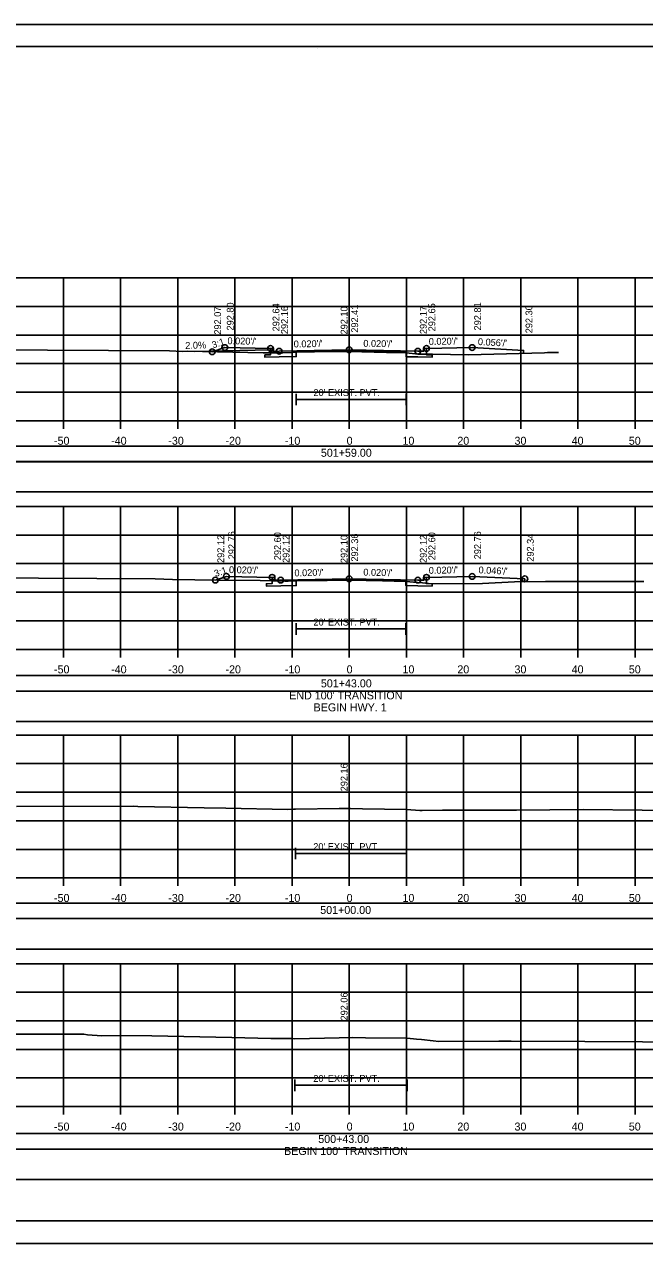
# Model space of a CAD drawing. Extents: x 1370538 to 1372872, y 376220 to 381127.
# Drawn here: x 1372651.8 to 1372760.3, y 376433.8 to 376647.1 of the extents above; entities that cross this region are included whole.
import ezdxf

# ---------------------------------------------------------------- set-up
doc = ezdxf.new("R2010")
doc.units = 0
for name, color, linetype in [('R_Border', 7, 'Continuous'), ('R_Border Notes', 7, 'Continuous'), ('R_Border PE', 7, 'Continuous'), ('R_Border Prem', 7, 'Continuous'), ('R_Dimension', 7, 'Continuous'), ('R_Fin Surface', 7, 'Continuous'), ('R_Grid', 7, 'Continuous'), ('R_No Plot', 7, 'Continuous'), ('R_Water', 7, 'Continuous'), ('R_Xsect Elev', 7, 'Continuous'), ('R_Xsect Slope', 7, 'Continuous'), ('T_Detection Zones', 7, 'Continuous')]:
    doc.layers.add(name, color=color, linetype=linetype)

msp = doc.modelspace()

# ---------------------------------------------------------------- linework, layer by layer
at = {"layer": 'R_Border'}
for p, q in [((1372699.38, 376582.48), (1372699.38, 376580.48)), ((1372699.38, 376581.48), (1372718.58, 376581.48)), ((1372718.58, 376582.48), (1372718.58, 376580.48)), ((1372699.38, 376542.32), (1372699.38, 376540.32)), ((1372699.38, 376541.32), (1372718.57, 376541.32)), ((1372718.57, 376542.32), (1372718.57, 376540.32)), ((1372699.23, 376503.04), (1372699.23, 376501.04)), ((1372718.67, 376503.04), (1372718.67, 376501.04)), ((1372699.23, 376502.04), (1372718.67, 376502.04)), ((1372699.13, 376462.47), (1372699.13, 376460.47)), ((1372718.78, 376462.47), (1372718.78, 376460.47)), ((1372699.13, 376461.47), (1372718.78, 376461.47))]:
    msp.add_line(p, q, dxfattribs=at)
for points in [[(1372722.15, 376590.4), (1372722.15, 376589.31), (1372723.15, 376589.29), (1372723.15, 376588.87), (1372720.65, 376588.92), (1372718.58, 376588.96), (1372718.58, 376589.79), (1372708.65, 376589.99), (1372699.38, 376589.8), (1372699.38, 376588.97), (1372696.38, 376588.91), (1372693.88, 376588.86), (1372693.88, 376589.28), (1372694.88, 376589.3), (1372694.88, 376590.39)], [(1372722.15, 376550.35), (1372722.15, 376549.26), (1372723.15, 376549.24), (1372723.15, 376548.82), (1372720.65, 376548.87), (1372718.57, 376548.91), (1372718.57, 376549.74), (1372708.65, 376549.94), (1372699.38, 376549.76), (1372699.38, 376548.92), (1372696.65, 376548.87), (1372694.15, 376548.82), (1372694.15, 376549.24), (1372695.15, 376549.26), (1372695.15, 376550.35)]]:
    msp.add_lwpolyline(points, dxfattribs=at)
at = {"layer": 'R_Border Notes'}
for p, q in [((1372550.65, 376643.21), (1372866.83, 376643.21)), ((1372703.17, 376642.95), (1372703.17, 376642.95)), ((1372703.17, 376642.95), (1372703.17, 376642.95)), ((1372866.83, 376437.75), (1372550.65, 376437.75))]:
    msp.add_line(p, q, dxfattribs=at)
at = {"layer": 'R_Border Prem'}
for p, q in [((1372558.65, 376577.75), (1372858.65, 376577.75)), ((1372658.65, 376576.35), (1372658.65, 376577.75)), ((1372668.65, 376576.35), (1372668.65, 376577.75)), ((1372678.65, 376576.35), (1372678.65, 376577.75)), ((1372688.65, 376576.35), (1372688.65, 376577.75)), ((1372698.65, 376576.35), (1372698.65, 376577.75)), ((1372708.65, 376576.35), (1372708.65, 376577.75)), ((1372718.65, 376576.35), (1372718.65, 376577.75)), ((1372728.65, 376576.35), (1372728.65, 376577.75)), ((1372738.65, 376576.35), (1372738.65, 376577.75)), ((1372748.65, 376576.35), (1372748.65, 376577.75)), ((1372758.65, 376576.35), (1372758.65, 376577.75)), ((1372558.65, 376537.75), (1372858.65, 376537.75)), ((1372658.65, 376536.35), (1372658.65, 376537.75)), ((1372668.65, 376536.35), (1372668.65, 376537.75)), ((1372678.65, 376536.35), (1372678.65, 376537.75)), ((1372688.65, 376536.35), (1372688.65, 376537.75)), ((1372698.65, 376536.35), (1372698.65, 376537.75)), ((1372708.65, 376536.35), (1372708.65, 376537.75)), ((1372718.65, 376536.35), (1372718.65, 376537.75)), ((1372728.65, 376536.35), (1372728.65, 376537.75)), ((1372738.65, 376536.35), (1372738.65, 376537.75)), ((1372748.65, 376536.35), (1372748.65, 376537.75)), ((1372758.65, 376536.35), (1372758.65, 376537.75)), ((1372558.65, 376497.75), (1372858.65, 376497.75)), ((1372658.65, 376496.35), (1372658.65, 376497.75)), ((1372668.65, 376496.35), (1372668.65, 376497.75)), ((1372678.65, 376496.35), (1372678.65, 376497.75)), ((1372688.65, 376496.35), (1372688.65, 376497.75)), ((1372698.65, 376496.35), (1372698.65, 376497.75)), ((1372708.65, 376496.35), (1372708.65, 376497.75)), ((1372718.65, 376496.35), (1372718.65, 376497.75)), ((1372728.65, 376496.35), (1372728.65, 376497.75)), ((1372738.65, 376496.35), (1372738.65, 376497.75)), ((1372748.65, 376496.35), (1372748.65, 376497.75)), ((1372758.65, 376496.35), (1372758.65, 376497.75)), ((1372558.65, 376457.75), (1372858.65, 376457.75)), ((1372658.65, 376456.35), (1372658.65, 376457.75)), ((1372668.65, 376456.35), (1372668.65, 376457.75)), ((1372678.65, 376456.35), (1372678.65, 376457.75)), ((1372688.65, 376456.35), (1372688.65, 376457.75)), ((1372698.65, 376456.35), (1372698.65, 376457.75)), ((1372708.65, 376456.35), (1372708.65, 376457.75)), ((1372718.65, 376456.35), (1372718.65, 376457.75)), ((1372728.65, 376456.35), (1372728.65, 376457.75)), ((1372738.65, 376456.35), (1372738.65, 376457.75)), ((1372748.65, 376456.35), (1372748.65, 376457.75)), ((1372758.65, 376456.35), (1372758.65, 376457.75))]:
    msp.add_line(p, q, dxfattribs=at)
at = {"layer": 'R_Dimension'}
for points in [[(1372602.41, 376590.38), (1372677.18, 376589.99), (1372679.5, 376589.89), (1372680.3, 376589.9), (1372693.58, 376589.65), (1372697.01, 376589.66), (1372698.59, 376589.71), (1372699.38, 376589.74), (1372702.58, 376589.79), (1372708.67, 376589.85), (1372715.18, 376589.69), (1372718.58, 376589.61), (1372720.75, 376589.43), (1372721.29, 376589.38), (1372723.23, 376589.38), (1372729.52, 376589.3), (1372742.79, 376589.65), (1372743.35, 376589.68), (1372743.98, 376589.69), (1372744.51, 376589.69), (1372745.24, 376589.69)], [(1372623.62, 376550.37), (1372674.71, 376550.11), (1372677.73, 376549.99), (1372685.54, 376549.87), (1372693.08, 376549.78), (1372697.37, 376549.71), (1372697.98, 376549.71), (1372699.38, 376549.75), (1372704.81, 376549.81), (1372708.7, 376549.85), (1372714.44, 376549.72), (1372718.57, 376549.63), (1372720.59, 376549.44), (1372721.49, 376549.38), (1372722.52, 376549.3), (1372723.29, 376549.2), (1372731.94, 376549.3), (1372737.55, 376549.57), (1372743.01, 376549.63), (1372744.67, 376549.64), (1372747.12, 376549.64), (1372747.84, 376549.64), (1372760.19, 376549.62)], [(1372650.44, 376510.24), (1372670.9, 376510.3), (1372671.63, 376510.26), (1372683.29, 376510.01), (1372687.07, 376509.96), (1372697.82, 376509.74), (1372698.88, 376509.76), (1372699.23, 376509.76), (1372706.86, 376509.88), (1372708.85, 376509.91), (1372710.97, 376509.87), (1372718.67, 376509.74), (1372720.97, 376509.58), (1372721.43, 376509.55), (1372724.97, 376509.59), (1372737.91, 376509.62), (1372749.59, 376509.71), (1372759.89, 376509.64), (1372770.62, 376509.57)], [(1372645.59, 376470.4), (1372662.23, 376470.4), (1372662.85, 376470.33), (1372665.35, 376470.13), (1372668.65, 376470.2), (1372674.1, 376470.13), (1372688.11, 376469.81), (1372694.94, 376469.67), (1372697.44, 376469.64), (1372698.7, 376469.64), (1372699.13, 376469.63), (1372706.87, 376469.78), (1372709.23, 376469.82), (1372711.52, 376469.79), (1372718.78, 376469.7), (1372720.41, 376469.55), (1372721.3, 376469.46), (1372723.31, 376469.24), (1372724.32, 376469.11), (1372734.8, 376469.19), (1372735.84, 376469.19), (1372736.07, 376469.19), (1372736.24, 376469.19), (1372736.98, 376469.19), (1372749.87, 376469.15), (1372759.96, 376469.09), (1372804.27, 376468.71)]]:
    msp.add_lwpolyline(points, dxfattribs=at)
at = {"layer": 'R_Fin Surface'}
msp.add_line((1372739.38, 376550.09), (1372739.38, 376549.59), dxfattribs=at)
for points in [[(1372684.67, 376589.82), (1372686.88, 376590.55), (1372694.88, 376590.39), (1372695.38, 376590.39), (1372695.38, 376589.89), (1372696.38, 376589.91), (1372708.65, 376590.16), (1372720.65, 376589.92), (1372721.65, 376589.9), (1372721.65, 376590.4), (1372722.15, 376590.4), (1372730.15, 376590.56)], [(1372739.14, 376589.56), (1372739.14, 376590.06), (1372730.15, 376590.56)], [(1372685.22, 376549.87), (1372687.15, 376550.51), (1372695.15, 376550.35), (1372695.65, 376550.35), (1372695.65, 376549.85), (1372696.65, 376549.87), (1372708.65, 376550.11), (1372720.65, 376549.87), (1372721.65, 376549.85), (1372721.65, 376550.35), (1372722.15, 376550.35), (1372730.15, 376550.51), (1372739.38, 376550.09)]]:
    msp.add_lwpolyline(points, dxfattribs=at)
at = {"layer": 'R_Grid'}
for p, q in [((1372558.65, 376602.75), (1372858.65, 376602.75)), ((1372658.65, 376577.75), (1372658.65, 376602.75)), ((1372668.65, 376577.75), (1372668.65, 376602.75)), ((1372678.65, 376577.75), (1372678.65, 376602.75)), ((1372688.65, 376577.75), (1372688.65, 376602.75)), ((1372698.65, 376577.75), (1372698.65, 376602.75)), ((1372708.65, 376577.75), (1372708.65, 376602.75)), ((1372718.65, 376577.75), (1372718.65, 376602.75)), ((1372728.65, 376577.75), (1372728.65, 376602.75)), ((1372738.65, 376577.75), (1372738.65, 376602.75)), ((1372748.65, 376577.75), (1372748.65, 376602.75)), ((1372758.65, 376577.75), (1372758.65, 376602.75)), ((1372558.65, 376597.75), (1372858.65, 376597.75)), ((1372558.65, 376592.75), (1372858.65, 376592.75)), ((1372558.65, 376587.75), (1372858.65, 376587.75)), ((1372558.65, 376582.75), (1372858.65, 376582.75)), ((1372558.65, 376577.75), (1372858.65, 376577.75)), ((1372558.65, 376562.75), (1372858.65, 376562.75)), ((1372658.65, 376537.75), (1372658.65, 376562.75)), ((1372668.65, 376537.75), (1372668.65, 376562.75)), ((1372678.65, 376537.75), (1372678.65, 376562.75)), ((1372688.65, 376537.75), (1372688.65, 376562.75)), ((1372698.65, 376537.75), (1372698.65, 376562.75)), ((1372708.65, 376537.75), (1372708.65, 376562.75)), ((1372718.65, 376537.75), (1372718.65, 376562.75)), ((1372728.65, 376537.75), (1372728.65, 376562.75)), ((1372738.65, 376537.75), (1372738.65, 376562.75)), ((1372748.65, 376537.75), (1372748.65, 376562.75)), ((1372758.65, 376537.75), (1372758.65, 376562.75)), ((1372558.65, 376557.75), (1372858.65, 376557.75)), ((1372558.65, 376552.75), (1372858.65, 376552.75)), ((1372558.65, 376547.75), (1372858.65, 376547.75)), ((1372558.65, 376542.75), (1372858.65, 376542.75)), ((1372558.65, 376537.75), (1372858.65, 376537.75)), ((1372558.65, 376522.75), (1372858.65, 376522.75)), ((1372658.65, 376497.75), (1372658.65, 376522.75)), ((1372668.65, 376497.75), (1372668.65, 376522.75)), ((1372678.65, 376497.75), (1372678.65, 376522.75)), ((1372688.65, 376497.75), (1372688.65, 376522.75)), ((1372698.65, 376497.75), (1372698.65, 376522.75)), ((1372708.65, 376497.75), (1372708.65, 376522.75)), ((1372718.65, 376497.75), (1372718.65, 376522.75)), ((1372728.65, 376497.75), (1372728.65, 376522.75)), ((1372738.65, 376497.75), (1372738.65, 376522.75)), ((1372748.65, 376497.75), (1372748.65, 376522.75)), ((1372758.65, 376497.75), (1372758.65, 376522.75)), ((1372558.65, 376517.75), (1372858.65, 376517.75)), ((1372558.65, 376512.75), (1372858.65, 376512.75)), ((1372558.65, 376507.75), (1372858.65, 376507.75)), ((1372558.65, 376502.75), (1372858.65, 376502.75)), ((1372558.65, 376497.75), (1372858.65, 376497.75)), ((1372558.65, 376482.75), (1372858.65, 376482.75)), ((1372658.65, 376457.75), (1372658.65, 376482.75)), ((1372668.65, 376457.75), (1372668.65, 376482.75)), ((1372678.65, 376457.75), (1372678.65, 376482.75)), ((1372688.65, 376457.75), (1372688.65, 376482.75)), ((1372698.65, 376457.75), (1372698.65, 376482.75)), ((1372708.65, 376457.75), (1372708.65, 376482.75)), ((1372718.65, 376457.75), (1372718.65, 376482.75)), ((1372728.65, 376457.75), (1372728.65, 376482.75)), ((1372738.65, 376457.75), (1372738.65, 376482.75)), ((1372748.65, 376457.75), (1372748.65, 376482.75)), ((1372758.65, 376457.75), (1372758.65, 376482.75)), ((1372558.65, 376477.75), (1372858.65, 376477.75)), ((1372558.65, 376472.75), (1372858.65, 376472.75)), ((1372558.65, 376467.75), (1372858.65, 376467.75)), ((1372558.65, 376462.75), (1372858.65, 376462.75)), ((1372558.65, 376457.75), (1372858.65, 376457.75))]:
    msp.add_line(p, q, dxfattribs=at)
at = {"layer": 'R_No Plot'}
for p, q in [((1372538.25, 376647.11), (1372871.58, 376647.11)), ((1372538.25, 376433.77), (1372871.58, 376433.77))]:
    msp.add_line(p, q, dxfattribs=at)
for points in [[(1372538.24, 376647.11), (1372871.58, 376647.11), (1372871.58, 376433.77), (1372538.24, 376433.77)], [(1372784.57, 376643.21), (1372784.57, 376633.33), (1372820.3, 376633.33), (1372820.3, 376630.41), (1372843.5, 376630.41), (1372843.5, 376606.08), (1372866.83, 376606.08), (1372866.83, 376437.75), (1372550.65, 376437.75), (1372550.65, 376643.21)]]:
    msp.add_lwpolyline(points, close=True, dxfattribs=at)
for centre in [(1372684.67, 376589.82), (1372686.88, 376590.55), (1372694.88, 376590.39), (1372696.38, 376589.91), (1372708.65, 376590.16), (1372720.65, 376589.92), (1372722.15, 376590.4), (1372730.15, 376590.56), (1372685.22, 376549.87), (1372687.15, 376550.51), (1372695.15, 376550.35), (1372696.65, 376549.87), (1372708.65, 376550.11), (1372720.65, 376549.87), (1372722.15, 376550.35), (1372730.15, 376550.51), (1372739.38, 376550.09)]:
    msp.add_circle(centre, 0.5, dxfattribs=at)
at = {"layer": 'R_Water'}
for p, q in [((1372694.88, 376590.14), (1372681.49, 376589.88)), ((1372695.38, 376589.89), (1372694.88, 376590.14))]:
    msp.add_line(p, q, dxfattribs=at)
at = {"layer": 'R_Xsect Elev'}
for p, q in [((1372708.65, 376589.85), (1372708.65, 376599.85)), ((1372708.65, 376549.85), (1372708.65, 376559.85)), ((1372708.65, 376509.91), (1372708.65, 376519.91)), ((1372708.65, 376469.81), (1372708.65, 376479.81))]:
    msp.add_line(p, q, dxfattribs=at)
at = {"layer": 'T_Detection Zones'}
for points in [[(1372552.66, 376570.62), (1372864.63, 376570.62), (1372864.63, 376573.33), (1372552.66, 376573.33)], [(1372552.71, 376565.34), (1372864.59, 376565.34), (1372864.59, 376570.58), (1372552.71, 376570.58)], [(1372552.66, 376530.44), (1372864.63, 376530.44), (1372864.63, 376533.15), (1372552.66, 376533.15)], [(1372552.66, 376525.12), (1372864.63, 376525.12), (1372864.63, 376530.44), (1372552.66, 376530.44)], [(1372552.66, 376490.65), (1372864.63, 376490.65), (1372864.63, 376493.35), (1372552.66, 376493.35)], [(1372552.66, 376485.32), (1372864.63, 376485.32), (1372864.63, 376490.65), (1372552.66, 376490.65)], [(1372552.66, 376450.32), (1372864.63, 376450.32), (1372864.63, 376453.03), (1372552.66, 376453.03)], [(1372552.66, 376445), (1372864.63, 376445), (1372864.63, 376450.32), (1372552.66, 376450.32)]]:
    msp.add_lwpolyline(points, close=True, dxfattribs=at)

# ---------------------------------------------------------------- texts
at = {"layer": 'R_Border PE'}
for s, p in [('-50', (1372656.99, 376573.55)), ('-40', (1372666.99, 376573.55)), ('-30', (1372676.99, 376573.55)), ('-20', (1372686.99, 376573.55)), ('-10', (1372697.38, 376573.55)), ('501+59.00', (1372703.68, 376571.45)), ('0', (1372708.19, 376573.55)), ('10', (1372717.96, 376573.55)), ('20', (1372727.56, 376573.55)), ('30', (1372737.56, 376573.55)), ('40', (1372747.56, 376573.55)), ('50', (1372757.56, 376573.55)), ('-50', (1372656.99, 376533.55)), ('-40', (1372666.99, 376533.55)), ('-30', (1372676.99, 376533.55)), ('-20', (1372686.99, 376533.55)), ('-10', (1372697.38, 376533.55)), ('0', (1372708.19, 376533.55)), ('10', (1372717.96, 376533.55)), ('20', (1372727.56, 376533.55)), ('30', (1372737.56, 376533.55)), ('40', (1372747.56, 376533.55)), ('50', (1372757.56, 376533.55)), ('501+43.00', (1372703.68, 376531.1)), ("END 100' TRANSITION", (1372698.14, 376529)), ('BEGIN HWY. 1', (1372702.41, 376526.9)), ('-50', (1372656.99, 376493.55)), ('-40', (1372666.99, 376493.55)), ('-30', (1372676.99, 376493.55)), ('-20', (1372686.99, 376493.55)), ('-10', (1372697.38, 376493.55)), ('0', (1372708.19, 376493.55)), ('10', (1372717.96, 376493.55)), ('20', (1372727.56, 376493.55)), ('30', (1372737.56, 376493.55)), ('40', (1372747.56, 376493.55)), ('50', (1372757.56, 376493.55)), ('501+00.00', (1372703.57, 376491.45)), ('-50', (1372656.99, 376453.55)), ('-40', (1372666.99, 376453.55)), ('-30', (1372676.99, 376453.55)), ('-20', (1372686.99, 376453.55)), ('-10', (1372697.38, 376453.55)), ('0', (1372708.19, 376453.55)), ('10', (1372717.96, 376453.55)), ('20', (1372727.56, 376453.55)), ('30', (1372737.56, 376453.55)), ('40', (1372747.56, 376453.55)), ('50', (1372757.56, 376453.55)), ('500+43.00', (1372703.23, 376451.38)), ("BEGIN 100' TRANSITION", (1372697.24, 376449.28))]:
    msp.add_text(s, height=1.4, dxfattribs=at).set_placement(p)
at = {"layer": 'R_Water'}
for p in [(1372702.39, 376582.08), (1372702.38, 376541.92), (1372702.35, 376502.64), (1372702.36, 376462.07)]:
    msp.add_text("20' EXIST. PVT.", height=1.2, dxfattribs=at).set_placement(p)
at = {"layer": 'R_Xsect Elev'}
for s, rotation, p in [('292.07', 90, (1372686.22, 376592.82)), ('292.80', 90, (1372688.43, 376593.55)), ('292.64', 90, (1372696.43, 376593.39)), ('292.16', 90, (1372697.93, 376592.91)), ('292.10', 90, (1372708.35, 376592.85)), ('292.41', 90, (1372710.2, 376593.16)), ('292.17', 90, (1372722.2, 376592.92)), ('292.65', 90, (1372723.7, 376593.4)), ('292.81', 90, (1372731.7, 376593.56)), ('292.30', 90, (1372740.69, 376593.06)), ("0.056'/'", 356.7996, (1372731.13, 376591.01)), ('2.0%', 1.1458, (1372679.96, 376590.33)), ('292.76', 90, (1372688.7, 376553.51)), ('292.60', 90, (1372696.7, 376553.35)), ('292.36', 90, (1372710.2, 376553.11)), ('292.60', 90, (1372723.7, 376553.35)), ('292.76', 90, (1372731.7, 376553.51)), ('292.34', 90, (1372740.93, 376553.09)), ('292.12', 90, (1372686.77, 376552.87)), ('292.12', 90, (1372698.2, 376552.87)), ('292.10', 90, (1372708.35, 376552.85)), ('292.12', 90, (1372722.2, 376552.87)), ('292.16', 90, (1372708.35, 376512.91)), ('292.06', 90, (1372708.35, 376472.81))]:
    msp.add_text(s, height=1.2, rotation=rotation, dxfattribs=at).set_placement(p)
at = {"layer": 'R_Xsect Slope'}
for s, rotation, p in [('3:1', 18.4349, (1372684.83, 376590.4)), ("0.020'/'", 358.8542, (1372687.33, 376591.15)), ("0.020'/'", 1.1458, (1372722.57, 376591.01)), ("0.020'/'", 1.1458, (1372698.94, 376590.57)), ("0.020'/'", 358.8542, (1372711.1, 376590.71)), ('3:1', 18.4349, (1372685.24, 376550.4)), ("0.020'/'", 358.8542, (1372687.6, 376551.1)), ("0.020'/'", 1.1458, (1372699.07, 376550.52)), ("0.020'/'", 358.8542, (1372711.1, 376550.66)), ("0.020'/'", 1.1458, (1372722.57, 376550.96)), ("0.046'/'", 357.3906, (1372731.25, 376551.06))]:
    msp.add_text(s, height=1.2, rotation=rotation, dxfattribs=at).set_placement(p)

doc.saveas('drawing.dxf')
